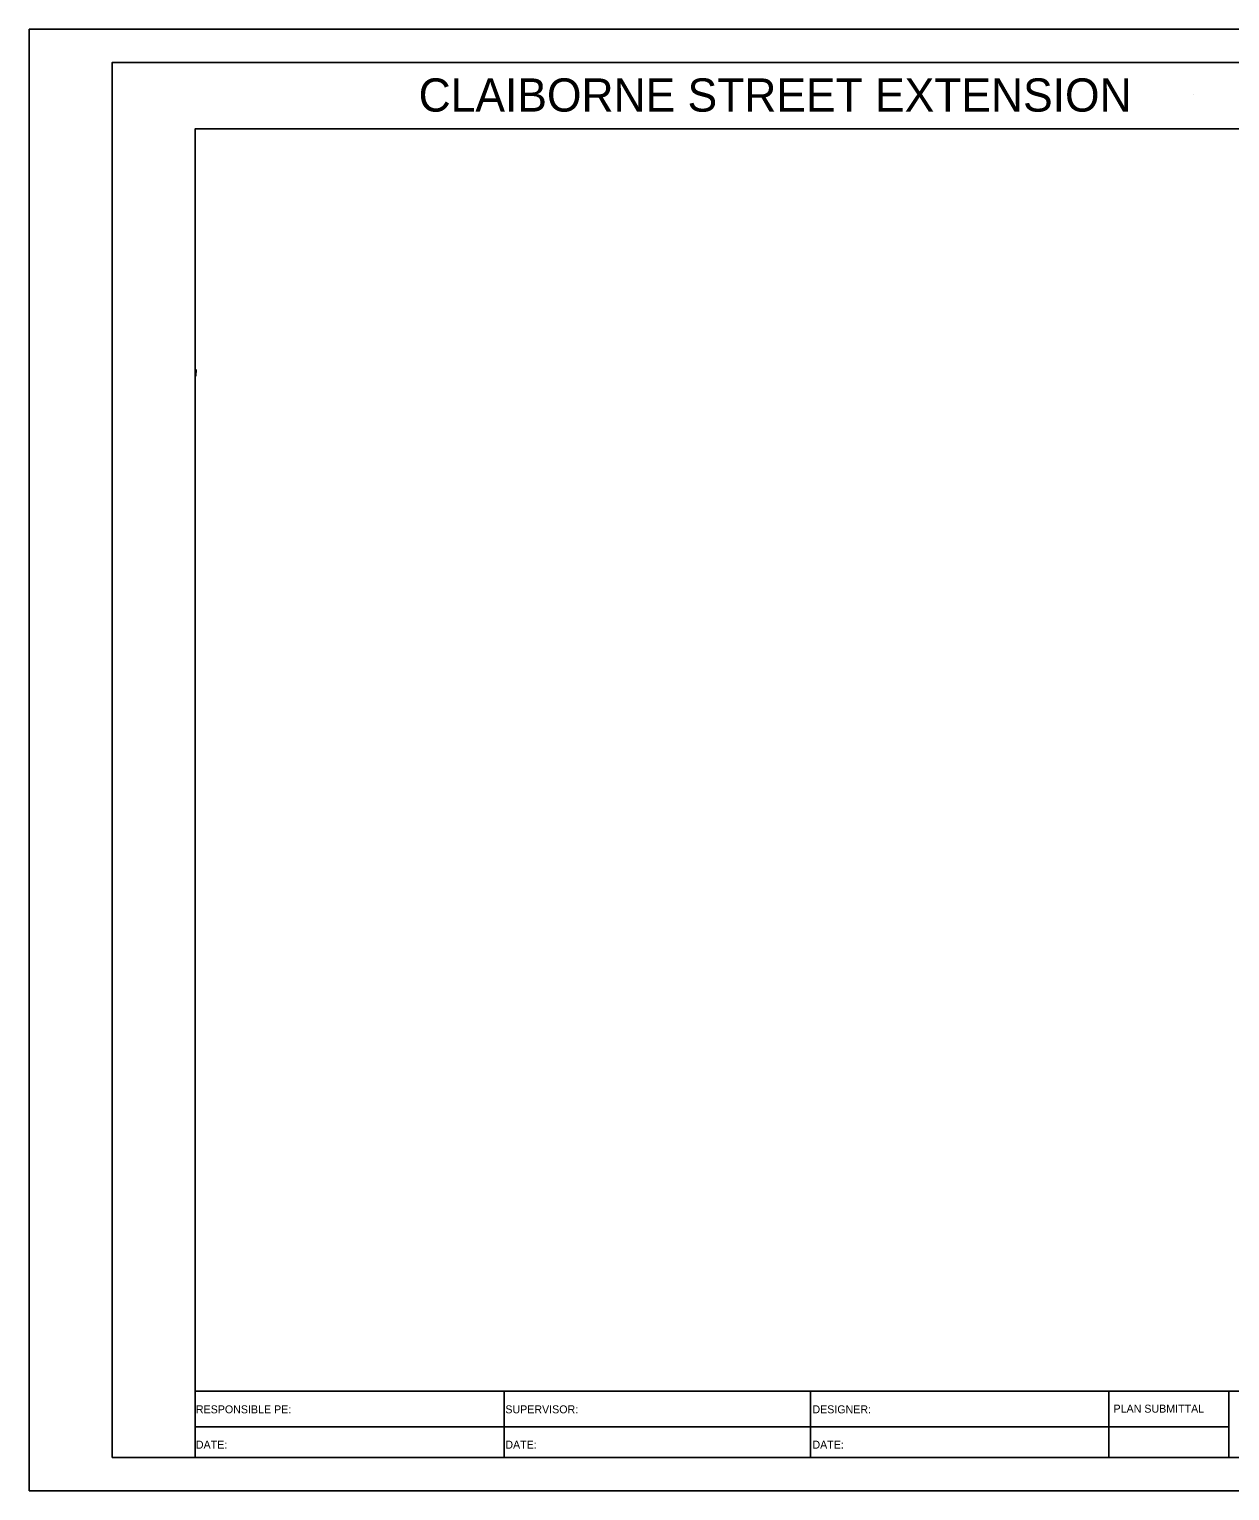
# Model space of a CAD drawing. Extents: x 1797478 to 1803816, y 246529 to 250952.
# Drawn here: x 1802116 to 1802296.8, y 250064.4 to 250284.4 of the extents above; entities that cross this region are included whole.
import ezdxf

# ---------------------------------------------------------------- set-up
doc = ezdxf.new("R2010")
doc.units = 0
for name, color, linetype in [('2', 7, 'Continuous'), ('ANNO-SHT', 7, 'Continuous'), ('ANNO-TXT', 7, 'Continuous'), ('AXIS', 7, 'Continuous'), ('DRAINAGE', 7, 'Continuous'), ('Level 1', 7, 'Continuous'), ('Level 62', 7, 'Continuous'), ('SHT-BDR', 7, 'Continuous'), ('SHT-BNDRY', 7, 'Continuous')]:
    doc.layers.add(name, color=color, linetype=linetype)

# ---------------------------------------------------------------- blocks, each defined once
blk = doc.blocks.new('SC47208')
at = {"layer": 'Level 1'}
blk.add_line((0, 0), (0, 0), dxfattribs=at)

msp = doc.modelspace()

# ---------------------------------------------------------------- linework, layer by layer
at = {"layer": '2'}
msp.add_lwpolyline([(1802141.12, 250233.21), (1802141.1, 250232.21)], dxfattribs=at)
msp.add_lwpolyline([(1802141.12, 250233.21), (1802141.1, 250232.21)], dxfattribs=at)
at = {"layer": 'AXIS'}
msp.add_line((1802141, 250189.42), (1802141, 250189.43), dxfattribs=at)
at = {"layer": 'Level 62'}
msp.add_lwpolyline([(1802116, 250064.42), (1802456, 250064.42), (1802456, 250284.42), (1802116, 250284.42)], close=True, dxfattribs=at)
at = {"layer": 'SHT-BDR'}
msp.add_lwpolyline([(1802141, 250079.43), (1802441, 250079.43), (1802441, 250269.43), (1802141, 250269.43)], close=True, dxfattribs=at)
at = {"layer": 'SHT-BNDRY'}
for p, q in [((1802141, 250069.42), (1802141, 250079.43)), ((1802187.52, 250079.43), (1802187.52, 250069.42)), ((1802233.67, 250069.42), (1802233.67, 250079.43)), ((1802278.59, 250069.42), (1802278.59, 250079.43)), ((1802296.63, 250069.42), (1802296.63, 250079.43)), ((1802141, 250074.03), (1802296.63, 250074.03))]:
    msp.add_line(p, q, dxfattribs=at)
msp.add_lwpolyline([(1802128.5, 250069.42), (1802451, 250069.42), (1802451, 250279.42), (1802128.5, 250279.42)], close=True, dxfattribs=at)

# ---------------------------------------------------------------- block references
at = {"layer": 'DRAINAGE', "xscale": 0.2, "yscale": 0.20000000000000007, "rotation": -116.41666666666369}
msp.add_blockref('SC47208', (1802291.32, 250274.62), dxfattribs=at)
msp.add_blockref('SC47208', (1802291.32, 250274.62), dxfattribs=at)

# ---------------------------------------------------------------- texts
at = {"layer": 'ANNO-SHT'}
msp.add_text('           CLAIBORNE STREET EXTENSION           ', height=4.9995, rotation=360, dxfattribs=at).set_placement((1802154.21, 250272.02))
at = {"layer": 'ANNO-TXT'}
for s, p in [('RESPONSIBLE PE:', (1802141.1, 250076.08)), ('SUPERVISOR:', (1802187.7, 250076.08)), ('DESIGNER:', (1802233.94, 250076.08)), ('PLAN SUBMITTAL', (1802279.28, 250076.18)), ('DATE:', (1802141.1, 250070.76)), ('DATE:', (1802187.7, 250070.76)), ('DATE:', (1802233.94, 250070.76))]:
    msp.add_text(s, height=1.2, rotation=360, dxfattribs=at).set_placement(p)

doc.saveas('drawing.dxf')
